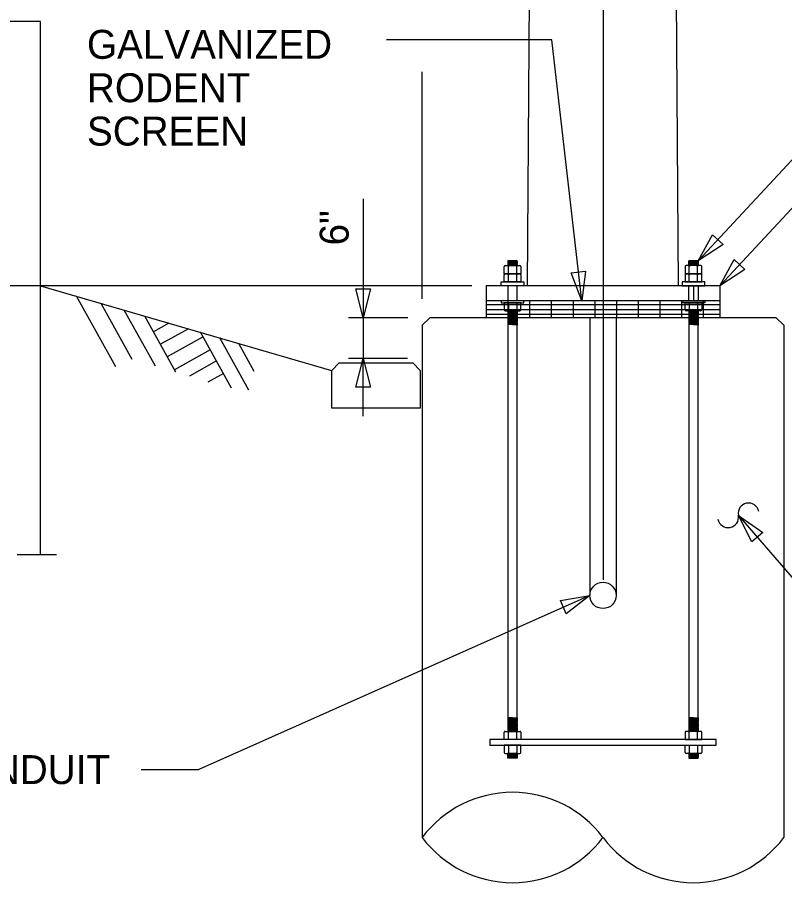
# Model space of a CAD drawing. Extents: x 1299104.7 to 1299141.5, y 239689.9 to 239711.9.
# Drawn here: x 1299109.189 to 1299112.372, y 239694.879 to 239698.469 of the extents above; entities that cross this region are included whole.
import ezdxf

# ---------------------------------------------------------------- set-up
doc = ezdxf.new("R2010")
doc.units = 0
for name, color, linetype in [('DIM TXT', 7, 'Continuous'), ('Level 3', 7, 'Continuous'), ('Level 4', 7, 'Continuous'), ('Level 6', 7, 'Continuous'), ('Level 7', 7, 'Continuous'), ('Level 8', 7, 'Continuous')]:
    doc.layers.add(name, color=color, linetype=linetype)

msp = doc.modelspace()

# ---------------------------------------------------------------- linework, layer by layer
at = {"layer": 'Level 3'}
for p, q in [((1299111.3057, 239697.3558), (1299111.3303, 239701.4808)), ((1299111.9307, 239697.3558), (1299111.9062, 239701.4808)), ((1299109.2861, 239698.4525), (1299109.0496, 239698.4525)), ((1299109.2861, 239697.3558), (1299109.2861, 239698.4525)), ((1299111.2261, 239697.4056), (1299111.2261, 239697.4397)), ((1299111.2603, 239697.4056), (1299111.2603, 239697.4397)), ((1299111.9761, 239697.4056), (1299111.9761, 239697.4397)), ((1299112.0103, 239697.4056), (1299112.0103, 239697.4397)), ((1299111.2261, 239697.3714), (1299111.2261, 239697.4056)), ((1299111.2603, 239697.3714), (1299111.2603, 239697.4056)), ((1299111.9761, 239697.3714), (1299111.9761, 239697.4056)), ((1299112.0103, 239697.3714), (1299112.0103, 239697.4056)), ((1299109.2861, 239697.3558), (1299110.4926, 239697.0044)), ((1299111.1338, 239697.3558), (1299111.1338, 239697.2933)), ((1299112.1026, 239697.3558), (1299111.1338, 239697.3558)), ((1299111.6182, 239697.3558), (1299111.3057, 239697.3558)), ((1299111.9932, 239697.3558), (1299111.9932, 239697.2933)), ((1299112.1026, 239697.3558), (1299112.1026, 239697.2933)), ((1299112.1026, 239697.2933), (1299111.1338, 239697.2933)), ((1299111.1338, 239697.2933), (1299111.1338, 239697.223)), ((1299111.1338, 239697.2774), (1299112.1026, 239697.2774)), ((1299111.2238, 239697.2933), (1299111.2238, 239697.223)), ((1299111.2261, 239697.2854), (1299111.2261, 239697.2513)), ((1299111.2603, 239697.2854), (1299111.2603, 239697.2513)), ((1299111.3138, 239697.2933), (1299111.3138, 239697.223)), ((1299111.4038, 239697.2933), (1299111.4038, 239697.223)), ((1299111.4938, 239697.2933), (1299111.4938, 239697.223)), ((1299111.5838, 239697.2933), (1299111.5838, 239697.223)), ((1299111.6738, 239697.2933), (1299111.6738, 239697.223)), ((1299111.7638, 239697.2933), (1299111.7638, 239697.223)), ((1299111.8538, 239697.2933), (1299111.8538, 239697.223)), ((1299111.9438, 239697.2933), (1299111.9438, 239697.223)), ((1299111.9761, 239697.2854), (1299111.9761, 239697.2513)), ((1299112.0103, 239697.2854), (1299112.0103, 239697.2513)), ((1299112.0338, 239697.2933), (1299112.0338, 239697.223)), ((1299112.1026, 239697.2933), (1299112.1026, 239697.223)), ((1299111.1338, 239697.2574), (1299112.1026, 239697.2574)), ((1299111.1338, 239697.2374), (1299112.1026, 239697.2374)), ((1299110.8995, 239697.2229), (1299110.8682, 239697.1917)), ((1299112.337, 239697.2229), (1299110.8995, 239697.2229)), ((1299111.5635, 239697.2229), (1299111.5635, 239696.071)), ((1299111.6729, 239697.2229), (1299111.6729, 239696.071)), ((1299112.337, 239697.2229), (1299112.3682, 239697.1917)), ((1299110.8682, 239697.1917), (1299110.8682, 239695.0667)), ((1299112.3682, 239697.1917), (1299112.3682, 239695.0667)), ((1299110.4932, 239697.0042), (1299110.5245, 239697.0354)), ((1299110.5245, 239697.0354), (1299110.8292, 239697.0354)), ((1299110.8292, 239697.0354), (1299110.8604, 239697.0042)), ((1299110.4932, 239696.8479), (1299110.4932, 239697.0042)), ((1299110.8604, 239697.0042), (1299110.8604, 239696.8479)), ((1299110.8604, 239696.8479), (1299110.4932, 239696.8479)), ((1299111.2261, 239695.4729), (1299111.2261, 239695.5071)), ((1299111.2603, 239695.4729), (1299111.2603, 239695.5071)), ((1299111.9761, 239695.4729), (1299111.9761, 239695.5071)), ((1299112.0103, 239695.4729), (1299112.0103, 239695.5071)), ((1299112.087, 239695.4729), (1299111.1495, 239695.4729)), ((1299111.1495, 239695.4729), (1299111.1495, 239695.4495)), ((1299112.087, 239695.4495), (1299112.087, 239695.4729)), ((1299111.1495, 239695.4495), (1299112.087, 239695.4495)), ((1299111.2261, 239695.4495), (1299111.2261, 239695.4153)), ((1299111.2603, 239695.4495), (1299111.2603, 239695.4153)), ((1299111.9761, 239695.4495), (1299111.9761, 239695.4153)), ((1299112.0103, 239695.4495), (1299112.0103, 239695.4153))]:
    msp.add_line(p, q, dxfattribs=at)
for points in [[(1299111.2628, 239697.4397), (1299111.2628, 239697.4593), (1299111.2237, 239697.4593), (1299111.2237, 239697.4397)], [(1299111.2628, 239697.4593), (1299111.2237, 239697.4593), (1299111.2628, 239697.4573), (1299111.2628, 239697.4554), (1299111.2237, 239697.4573), (1299111.2237, 239697.4554), (1299111.2628, 239697.4534), (1299111.2628, 239697.4515), (1299111.2237, 239697.4534), (1299111.2237, 239697.4515), (1299111.2628, 239697.4495), (1299111.2628, 239697.4476), (1299111.2237, 239697.4495), (1299111.2237, 239697.4476), (1299111.2628, 239697.4456), (1299111.2628, 239697.4436), (1299111.2237, 239697.4456), (1299111.2237, 239697.4436), (1299111.2628, 239697.4417), (1299111.2628, 239697.4397), (1299111.2237, 239697.4417), (1299111.2237, 239697.4397)], [(1299111.9737, 239697.4397), (1299111.9737, 239697.4593), (1299112.0128, 239697.4593), (1299112.0128, 239697.4397)], [(1299112.0128, 239697.4593), (1299111.9737, 239697.4593), (1299112.0128, 239697.4573), (1299112.0128, 239697.4554), (1299111.9737, 239697.4573), (1299111.9737, 239697.4554), (1299112.0128, 239697.4534), (1299112.0128, 239697.4515), (1299111.9737, 239697.4534), (1299111.9737, 239697.4515), (1299112.0128, 239697.4495), (1299112.0128, 239697.4476), (1299111.9737, 239697.4495), (1299111.9737, 239697.4476), (1299112.0128, 239697.4456), (1299112.0128, 239697.4436), (1299111.9737, 239697.4456), (1299111.9737, 239697.4436), (1299112.0128, 239697.4417), (1299112.0128, 239697.4397), (1299111.9737, 239697.4417), (1299111.9737, 239697.4397)], [(1299111.2774, 239697.4357), (1299111.2774, 239697.4056), (1299111.209, 239697.4056), (1299111.209, 239697.4357)], [(1299111.213, 239697.4397), (1299111.2734, 239697.4397)], [(1299111.959, 239697.4357), (1299111.959, 239697.4056), (1299112.0274, 239697.4056), (1299112.0274, 239697.4357)], [(1299112.0234, 239697.4397), (1299111.963, 239697.4397)], [(1299111.2774, 239697.4016), (1299111.2774, 239697.3714), (1299111.209, 239697.3714), (1299111.209, 239697.4016)], [(1299111.213, 239697.4056), (1299111.2734, 239697.4056)], [(1299111.959, 239697.4016), (1299111.959, 239697.3714), (1299112.0274, 239697.3714), (1299112.0274, 239697.4016)], [(1299112.0234, 239697.4056), (1299111.963, 239697.4056)], [(1299111.2628, 239697.2933), (1299111.2628, 239697.3558), (1299111.2237, 239697.3558), (1299111.2237, 239697.2933)], [(1299111.9737, 239697.2933), (1299111.9737, 239697.3558), (1299112.0128, 239697.3558), (1299112.0128, 239697.2933)], [(1299111.2774, 239697.2553), (1299111.2774, 239697.2854), (1299111.209, 239697.2854), (1299111.209, 239697.2553)], [(1299111.959, 239697.2553), (1299111.959, 239697.2854), (1299112.0274, 239697.2854), (1299112.0274, 239697.2553)], [(1299111.213, 239697.2513), (1299111.2734, 239697.2513)], [(1299111.2628, 239695.5071), (1299111.2628, 239697.2513), (1299111.2237, 239697.2513), (1299111.2237, 239695.5071)], [(1299111.2628, 239697.2513), (1299111.2237, 239697.2513), (1299111.2628, 239697.2493), (1299111.2628, 239697.2474), (1299111.2237, 239697.2493), (1299111.2237, 239697.2474), (1299111.2628, 239697.2454), (1299111.2628, 239697.2435), (1299111.2237, 239697.2454), (1299111.2237, 239697.2435), (1299111.2628, 239697.2415), (1299111.2628, 239697.2395), (1299111.2237, 239697.2415), (1299111.2237, 239697.2395), (1299111.2628, 239697.2376), (1299111.2628, 239697.2356), (1299111.2237, 239697.2376), (1299111.2237, 239697.2356), (1299111.2628, 239697.2337), (1299111.2628, 239697.2317), (1299111.2237, 239697.2337), (1299111.2237, 239697.2317)], [(1299111.2237, 239697.2317), (1299111.2628, 239697.2298), (1299111.2628, 239697.2278), (1299111.2237, 239697.2298), (1299111.2237, 239697.2278), (1299111.2628, 239697.2259), (1299111.2628, 239697.2239), (1299111.2237, 239697.2259), (1299111.2237, 239697.2239), (1299111.2628, 239697.222), (1299111.2628, 239697.22), (1299111.2237, 239697.222), (1299111.2237, 239697.22), (1299111.2628, 239697.2181), (1299111.2628, 239697.2161), (1299111.2237, 239697.2181), (1299111.2237, 239697.2161), (1299111.2628, 239697.2142), (1299111.2628, 239697.2122), (1299111.2237, 239697.2142), (1299111.2237, 239697.2122)], [(1299112.0234, 239697.2513), (1299111.963, 239697.2513)], [(1299112.0128, 239695.5071), (1299112.0128, 239697.2513), (1299111.9737, 239697.2513), (1299111.9737, 239695.5071)], [(1299112.0128, 239697.2513), (1299111.9737, 239697.2513), (1299112.0128, 239697.2493), (1299112.0128, 239697.2474), (1299111.9737, 239697.2493), (1299111.9737, 239697.2474), (1299112.0128, 239697.2454), (1299112.0128, 239697.2435), (1299111.9737, 239697.2454), (1299111.9737, 239697.2435), (1299112.0128, 239697.2415), (1299112.0128, 239697.2395), (1299111.9737, 239697.2415), (1299111.9737, 239697.2395), (1299112.0128, 239697.2376), (1299112.0128, 239697.2356), (1299111.9737, 239697.2376), (1299111.9737, 239697.2356), (1299112.0128, 239697.2337), (1299112.0128, 239697.2317), (1299111.9737, 239697.2337), (1299111.9737, 239697.2317)], [(1299111.9737, 239697.2317), (1299112.0128, 239697.2298), (1299112.0128, 239697.2278), (1299111.9737, 239697.2298), (1299111.9737, 239697.2278), (1299112.0128, 239697.2259), (1299112.0128, 239697.2239), (1299111.9737, 239697.2259), (1299111.9737, 239697.2239), (1299112.0128, 239697.222), (1299112.0128, 239697.22), (1299111.9737, 239697.222), (1299111.9737, 239697.22), (1299112.0128, 239697.2181), (1299112.0128, 239697.2161), (1299111.9737, 239697.2181), (1299111.9737, 239697.2161), (1299112.0128, 239697.2142), (1299112.0128, 239697.2122), (1299111.9737, 239697.2142), (1299111.9737, 239697.2122)], [(1299111.2237, 239697.2122), (1299111.2628, 239697.2102), (1299111.2628, 239697.2083), (1299111.2237, 239697.2102), (1299111.2237, 239697.2083), (1299111.2628, 239697.2063), (1299111.2628, 239697.2044), (1299111.2237, 239697.2063), (1299111.2237, 239697.2044), (1299111.2628, 239697.2024), (1299111.2628, 239697.2005), (1299111.2237, 239697.2024), (1299111.2237, 239697.2005), (1299111.2628, 239697.1985), (1299111.2628, 239697.1966), (1299111.2237, 239697.1985), (1299111.2237, 239697.1966), (1299111.2628, 239697.1946), (1299111.2628, 239697.1927), (1299111.2237, 239697.1946), (1299111.2237, 239697.1927)], [(1299111.9737, 239697.2122), (1299112.0128, 239697.2102), (1299112.0128, 239697.2083), (1299111.9737, 239697.2102), (1299111.9737, 239697.2083), (1299112.0128, 239697.2063), (1299112.0128, 239697.2044), (1299111.9737, 239697.2063), (1299111.9737, 239697.2044), (1299112.0128, 239697.2024), (1299112.0128, 239697.2005), (1299111.9737, 239697.2024), (1299111.9737, 239697.2005), (1299112.0128, 239697.1985), (1299112.0128, 239697.1966), (1299111.9737, 239697.1985), (1299111.9737, 239697.1966), (1299112.0128, 239697.1946), (1299112.0128, 239697.1927), (1299111.9737, 239697.1946), (1299111.9737, 239697.1927)], [(1299111.213, 239695.5071), (1299111.2734, 239695.5071)], [(1299112.0234, 239695.5071), (1299111.963, 239695.5071)], [(1299111.2774, 239695.5031), (1299111.2774, 239695.4729), (1299111.209, 239695.4729), (1299111.209, 239695.5031)], [(1299111.959, 239695.5031), (1299111.959, 239695.4729), (1299112.0274, 239695.4729), (1299112.0274, 239695.5031)], [(1299111.2774, 239695.4193), (1299111.2774, 239695.4495), (1299111.209, 239695.4495), (1299111.209, 239695.4193)], [(1299111.959, 239695.4193), (1299111.959, 239695.4495), (1299112.0274, 239695.4495), (1299112.0274, 239695.4193)], [(1299111.213, 239695.4153), (1299111.2734, 239695.4153)], [(1299111.2628, 239695.4153), (1299111.2628, 239695.3958), (1299111.2237, 239695.3958), (1299111.2237, 239695.4153)], [(1299112.0234, 239695.4153), (1299111.963, 239695.4153)], [(1299111.9737, 239695.4153), (1299111.9737, 239695.3958), (1299112.0128, 239695.3958), (1299112.0128, 239695.4153)]]:
    msp.add_lwpolyline(points, dxfattribs=at)
for points in [[(1299111.2901, 239697.3558), (1299111.1963, 239697.3558), (1299111.1963, 239697.3714), (1299111.2901, 239697.3714)], [(1299111.9463, 239697.3558), (1299112.0401, 239697.3558), (1299112.0401, 239697.3714), (1299111.9463, 239697.3714)], [(1299111.2901, 239697.2933), (1299111.1963, 239697.2933), (1299111.1963, 239697.2854), (1299111.2901, 239697.2854)], [(1299111.9463, 239697.2933), (1299112.0401, 239697.2933), (1299112.0401, 239697.2854), (1299111.9463, 239697.2854)]]:
    msp.add_lwpolyline(points, close=True, dxfattribs=at)
msp.add_circle((1299111.6182, 239696.071), 0.0547, dxfattribs=at)
for centre, radius, start, end in [((1299111.213, 239697.4357), 0.004, 90, 180), ((1299111.2221, 239697.4357), 0.004, 0, 90), ((1299111.2643, 239697.4357), 0.004, 90, 180), ((1299111.2734, 239697.4357), 0.004, 0, 90), ((1299111.963, 239697.4357), 0.004, 90, 180), ((1299111.9721, 239697.4357), 0.004, 0, 90), ((1299112.0143, 239697.4357), 0.004, 90, 180), ((1299112.0234, 239697.4357), 0.004, 0, 90), ((1299111.213, 239697.4016), 0.004, 90, 180), ((1299111.2221, 239697.4016), 0.004, 0, 90), ((1299111.2643, 239697.4016), 0.004, 90, 180), ((1299111.2734, 239697.4016), 0.004, 0, 90), ((1299111.963, 239697.4016), 0.004, 90, 180), ((1299111.9721, 239697.4016), 0.004, 0, 90), ((1299112.0143, 239697.4016), 0.004, 90, 180), ((1299112.0234, 239697.4016), 0.004, 0, 90), ((1299111.213, 239697.2553), 0.004, 180, 270), ((1299111.2221, 239697.2553), 0.004, 270, 360), ((1299111.2643, 239697.2553), 0.004, 180, 270), ((1299111.2734, 239697.2553), 0.004, 270, 360), ((1299111.963, 239697.2553), 0.004, 180, 270), ((1299111.9721, 239697.2553), 0.004, 270, 360), ((1299112.0143, 239697.2553), 0.004, 180, 270), ((1299112.0234, 239697.2553), 0.004, 270, 360), ((1299111.213, 239695.5031), 0.004, 90, 180), ((1299111.2221, 239695.5031), 0.004, 0, 90), ((1299111.2643, 239695.5031), 0.004, 90, 180), ((1299111.2734, 239695.5031), 0.004, 0, 90), ((1299111.963, 239695.5031), 0.004, 90, 180), ((1299111.9721, 239695.5031), 0.004, 0, 90), ((1299112.0143, 239695.5031), 0.004, 90, 180), ((1299112.0234, 239695.5031), 0.004, 0, 90), ((1299111.213, 239695.4193), 0.004, 180, 270), ((1299111.2221, 239695.4193), 0.004, 270, 360), ((1299111.2643, 239695.4193), 0.004, 180, 270), ((1299111.2734, 239695.4193), 0.004, 270, 360), ((1299111.963, 239695.4193), 0.004, 180, 270), ((1299111.9721, 239695.4193), 0.004, 270, 360), ((1299112.0143, 239695.4193), 0.004, 180, 270), ((1299112.0234, 239695.4193), 0.004, 270, 360), ((1299111.2432, 239694.7854), 0.4687, 36.8699, 143.1301), ((1299111.2432, 239695.3479), 0.4687, 216.8699, 323.1301), ((1299111.9932, 239695.3479), 0.4687, 216.8699, 323.1301)]:
    msp.add_arc(centre, radius, start, end, dxfattribs=at)
for centre, major_axis, start_param, end_param in [((1299111.2372, 239697.4357), (-0.011, 0), 4.712389, 6.283185), ((1299111.2493, 239697.4357), (0.011, 0), 0, 1.570796), ((1299111.9872, 239697.4357), (-0.011, 0), 4.712389, 6.283185), ((1299111.9993, 239697.4357), (0.011, 0), 0, 1.570796), ((1299111.2372, 239697.4016), (-0.011, 0), 4.712389, 6.283185), ((1299111.2493, 239697.4016), (0.011, 0), 0, 1.570796), ((1299111.9872, 239697.4016), (-0.011, 0), 4.712389, 6.283185), ((1299111.9993, 239697.4016), (0.011, 0), 0, 1.570796), ((1299111.2372, 239697.2553), (-0.011, 0), 0, 1.570796), ((1299111.2493, 239697.2553), (0.011, 0), 4.712389, 6.283185), ((1299111.9872, 239697.2553), (-0.011, 0), 0, 1.570796), ((1299111.9993, 239697.2553), (0.011, 0), 4.712389, 6.283185), ((1299111.2372, 239695.5031), (-0.011, 0), 4.712389, 6.283185), ((1299111.2493, 239695.5031), (0.011, 0), 0, 1.570796), ((1299111.9872, 239695.5031), (-0.011, 0), 4.712389, 6.283185), ((1299111.9993, 239695.5031), (0.011, 0), 0, 1.570796), ((1299111.2372, 239695.4193), (-0.011, 0), 0, 1.570796), ((1299111.2493, 239695.4193), (0.011, 0), 4.712389, 6.283185), ((1299111.9872, 239695.4193), (-0.011, 0), 0, 1.570796), ((1299111.9993, 239695.4193), (0.011, 0), 4.712389, 6.283185)]:
    msp.add_ellipse(centre, major_axis=major_axis, ratio=0.362172, start_param=start_param, end_param=end_param, dxfattribs=at)
at = {"layer": 'Level 4'}
for points in [[(1299111.2237, 239695.5657), (1299111.2628, 239695.5638), (1299111.2628, 239695.5618), (1299111.2237, 239695.5638), (1299111.2237, 239695.5618), (1299111.2628, 239695.5599), (1299111.2628, 239695.5579), (1299111.2237, 239695.5599), (1299111.2237, 239695.5579), (1299111.2628, 239695.556), (1299111.2628, 239695.554), (1299111.2237, 239695.556), (1299111.2237, 239695.554), (1299111.2628, 239695.552), (1299111.2628, 239695.5501), (1299111.2237, 239695.552), (1299111.2237, 239695.5501), (1299111.2628, 239695.5481), (1299111.2628, 239695.5462), (1299111.2237, 239695.5481), (1299111.2237, 239695.5462)], [(1299111.2237, 239695.5462), (1299111.2628, 239695.5442), (1299111.2628, 239695.5423), (1299111.2237, 239695.5442), (1299111.2237, 239695.5423), (1299111.2628, 239695.5403), (1299111.2628, 239695.5384), (1299111.2237, 239695.5403), (1299111.2237, 239695.5384), (1299111.2628, 239695.5364), (1299111.2628, 239695.5345), (1299111.2237, 239695.5364), (1299111.2237, 239695.5345), (1299111.2628, 239695.5325), (1299111.2628, 239695.5306), (1299111.2237, 239695.5325), (1299111.2237, 239695.5306), (1299111.2628, 239695.5286), (1299111.2628, 239695.5267), (1299111.2237, 239695.5286), (1299111.2237, 239695.5267)], [(1299111.9737, 239695.5657), (1299112.0128, 239695.5638), (1299112.0128, 239695.5618), (1299111.9737, 239695.5638), (1299111.9737, 239695.5618), (1299112.0128, 239695.5599), (1299112.0128, 239695.5579), (1299111.9737, 239695.5599), (1299111.9737, 239695.5579), (1299112.0128, 239695.556), (1299112.0128, 239695.554), (1299111.9737, 239695.556), (1299111.9737, 239695.554), (1299112.0128, 239695.552), (1299112.0128, 239695.5501), (1299111.9737, 239695.552), (1299111.9737, 239695.5501), (1299112.0128, 239695.5481), (1299112.0128, 239695.5462), (1299111.9737, 239695.5481), (1299111.9737, 239695.5462)], [(1299111.9737, 239695.5462), (1299112.0128, 239695.5442), (1299112.0128, 239695.5423), (1299111.9737, 239695.5442), (1299111.9737, 239695.5423), (1299112.0128, 239695.5403), (1299112.0128, 239695.5384), (1299111.9737, 239695.5403), (1299111.9737, 239695.5384), (1299112.0128, 239695.5364), (1299112.0128, 239695.5345), (1299111.9737, 239695.5364), (1299111.9737, 239695.5345), (1299112.0128, 239695.5325), (1299112.0128, 239695.5306), (1299111.9737, 239695.5325), (1299111.9737, 239695.5306), (1299112.0128, 239695.5286), (1299112.0128, 239695.5267), (1299111.9737, 239695.5286), (1299111.9737, 239695.5267)], [(1299111.2237, 239695.5267), (1299111.2628, 239695.5247), (1299111.2628, 239695.5227), (1299111.2237, 239695.5247), (1299111.2237, 239695.5227), (1299111.2628, 239695.5208), (1299111.2628, 239695.5188), (1299111.2237, 239695.5208), (1299111.2237, 239695.5188), (1299111.2628, 239695.5169), (1299111.2628, 239695.5149), (1299111.2237, 239695.5169), (1299111.2237, 239695.5149), (1299111.2628, 239695.513), (1299111.2628, 239695.511), (1299111.2237, 239695.513), (1299111.2237, 239695.511), (1299111.2628, 239695.5091), (1299111.2628, 239695.5071), (1299111.2237, 239695.5091), (1299111.2237, 239695.5071)], [(1299111.9737, 239695.5267), (1299112.0128, 239695.5247), (1299112.0128, 239695.5227), (1299111.9737, 239695.5247), (1299111.9737, 239695.5227), (1299112.0128, 239695.5208), (1299112.0128, 239695.5188), (1299111.9737, 239695.5208), (1299111.9737, 239695.5188), (1299112.0128, 239695.5169), (1299112.0128, 239695.5149), (1299111.9737, 239695.5169), (1299111.9737, 239695.5149), (1299112.0128, 239695.513), (1299112.0128, 239695.511), (1299111.9737, 239695.513), (1299111.9737, 239695.511), (1299112.0128, 239695.5091), (1299112.0128, 239695.5071), (1299111.9737, 239695.5091), (1299111.9737, 239695.5071)], [(1299111.2628, 239695.4153), (1299111.2237, 239695.4153), (1299111.2628, 239695.4134), (1299111.2628, 239695.4114), (1299111.2237, 239695.4134), (1299111.2237, 239695.4114), (1299111.2628, 239695.4095), (1299111.2628, 239695.4075), (1299111.2237, 239695.4095), (1299111.2237, 239695.4075), (1299111.2628, 239695.4056), (1299111.2628, 239695.4036), (1299111.2237, 239695.4056), (1299111.2237, 239695.4036), (1299111.2628, 239695.4017), (1299111.2628, 239695.3997), (1299111.2237, 239695.4017), (1299111.2237, 239695.3997), (1299111.2628, 239695.3977), (1299111.2628, 239695.3958), (1299111.2237, 239695.3977), (1299111.2237, 239695.3958)], [(1299112.0128, 239695.4153), (1299111.9737, 239695.4153), (1299112.0128, 239695.4134), (1299112.0128, 239695.4114), (1299111.9737, 239695.4134), (1299111.9737, 239695.4114), (1299112.0128, 239695.4095), (1299112.0128, 239695.4075), (1299111.9737, 239695.4095), (1299111.9737, 239695.4075), (1299112.0128, 239695.4056), (1299112.0128, 239695.4036), (1299111.9737, 239695.4056), (1299111.9737, 239695.4036), (1299112.0128, 239695.4017), (1299112.0128, 239695.3997), (1299111.9737, 239695.4017), (1299111.9737, 239695.3997), (1299112.0128, 239695.3977), (1299112.0128, 239695.3958), (1299111.9737, 239695.3977), (1299111.9737, 239695.3958)]]:
    msp.add_lwpolyline(points, dxfattribs=at)
at = {"layer": 'Level 6'}
msp.add_line((1299109.2861, 239696.2398), (1299109.2861, 239697.3558), dxfattribs=at)
at = {"layer": 'Level 7'}
msp.add_line((1299111.6182, 239710.05), (1299111.6182, 239696.1358), dxfattribs=at)
at = {"layer": 'Level 8'}
for p, q in [((1299112.0128, 239697.4593), (1299113.5843, 239699.151)), ((1299112.1026, 239697.3558), (1299113.4699, 239698.8276)), ((1299110.8682, 239697.3018), (1299110.8682, 239698.243)), ((1299110.6234, 239697.7157), (1299110.6234, 239697.2229)), ((1299111.0738, 239697.3558), (1299106.7127, 239697.3558)), ((1299109.5972, 239697.0192), (1299109.4349, 239697.3124)), ((1299109.6662, 239697.0495), (1299109.5371, 239697.2827)), ((1299109.7617, 239697.0217), (1299109.6326, 239697.2549)), ((1299109.8465, 239696.9973), (1299109.7176, 239697.2301)), ((1299109.8182, 239697.2008), (1299109.7536, 239697.165)), ((1299110.8082, 239697.2229), (1299110.5634, 239697.2229)), ((1299110.6234, 239697.2229), (1299110.6234, 239697.0543)), ((1299109.899, 239697.1773), (1299109.7832, 239697.1131)), ((1299110.0775, 239696.931), (1299109.9493, 239697.1626)), ((1299109.9599, 239697.1435), (1299109.8106, 239697.0608)), ((1299110.1494, 239696.923), (1299110.0297, 239697.1392)), ((1299109.9897, 239697.0895), (1299109.8416, 239697.0075)), ((1299110.1721, 239697.0001), (1299110.1076, 239697.1165)), ((1299110.8076, 239697.0543), (1299110.5634, 239697.0543)), ((1299110.6234, 239696.8143), (1299110.6234, 239697.0543)), ((1299110.0152, 239697.0435), (1299109.9027, 239696.9812)), ((1299110.0437, 239696.9919), (1299109.9795, 239696.9562)), ((1299112.1796, 239696.4032), (1299112.6765, 239695.8269)), ((1299109.3521, 239696.2398), (1299109.1893, 239696.2398)), ((1299111.5635, 239696.071), (1299109.9423, 239695.3484)), ((1299109.7023, 239695.3484), (1299109.9423, 239695.3484))]:
    msp.add_line(p, q, dxfattribs=at)
msp.add_lwpolyline([(1299111.53, 239697.2933), (1299111.4059, 239698.3763), (1299110.7206, 239698.3763)], dxfattribs=at)
for points in [[(1299112.1164, 239697.5268), (1299112.0128, 239697.4593), (1299112.0724, 239697.5676)], [(1299112.2062, 239697.4233), (1299112.1026, 239697.3558), (1299112.1623, 239697.4641)], [(1299111.5462, 239697.4159), (1299111.53, 239697.2933), (1299111.4865, 239697.4091)], [(1299110.6534, 239697.3429), (1299110.6234, 239697.2229), (1299110.5934, 239697.3429)], [(1299110.5934, 239696.9343), (1299110.6234, 239697.0543), (1299110.6534, 239696.9343)], [(1299112.2353, 239696.2927), (1299112.1796, 239696.4032), (1299112.2807, 239696.3319)], [(1299111.4417, 239696.0496), (1299111.5635, 239696.071), (1299111.4661, 239695.9948)]]:
    msp.add_lwpolyline(points, close=True, dxfattribs=at)
for centre, start, end in [((1299112.2219, 239696.4113), 10.7666, 190.7666), ((1299112.1373, 239696.3952), 190.7666, 10.7666)]:
    msp.add_arc(centre, 0.043, start, end, dxfattribs=at)

# ---------------------------------------------------------------- texts
at = {"layer": 'DIM TXT'}
for s, p in [('GALVANIZED', (1299109.4781, 239698.2972)), ('RODENT', (1299109.4781, 239698.1172)), ('SCREEN', (1299109.4781, 239697.9372)), ('CONDUIT', (1299108.843, 239695.2884))]:
    msp.add_text(s, height=0.12, dxfattribs=at).set_placement(p)
msp.add_text('6"', height=0.12, rotation=90, dxfattribs=at).set_placement((1299110.5634, 239697.5229))

doc.saveas('drawing.dxf')
